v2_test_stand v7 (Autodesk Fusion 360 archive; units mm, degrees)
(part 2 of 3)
sketch "Sketch15" plane through (0, 327.4208, 0) normal (0, 1, 0) x axis (-1, 0, 0)
  line L1 (8.9053, 183.5) -> (8.9053, 201.5)
  line L2 (1.5053, 182.2) -> (7.6053, 182.2)
  line L3 (1.5053, 184.6) -> (1.5053, 182.2)
  line L4 (2.6553, 184.6) -> (1.5053, 184.6)
  line L5 (2.6553, 187.0757) -> (2.6553, 184.6)
  line L6 (1.4897, 188.2414) -> (2.6553, 187.0757)
  line L7 (-4.1375, 188.3) -> (1.3482, 188.3)
  line L8 (-5.4447, 187.0757) -> (-4.279, 188.2414)
  line L9 (-5.4447, 184.6) -> (-5.4447, 187.0757)
  line L10 (-4.2947, 184.6) -> (-5.4447, 184.6)
  line L11 (-4.2947, 182.2) -> (-4.2947, 184.6)
  line L12 (-10.3947, 182.2) -> (-4.2947, 182.2)
  line L13 (-11.6947, 201.5) -> (-11.6947, 183.5)
  line L14 (-4.2947, 202.8) -> (-10.3947, 202.8)
  line L15 (-4.2947, 200.4) -> (-4.2947, 202.8)
  line L16 (-5.4447, 200.4) -> (-4.2947, 200.4)
  line L17 (-5.4447, 197.9243) -> (-5.4447, 200.4)
  line L18 (-4.279, 196.7586) -> (-5.4447, 197.9243)
  line L19 (1.3482, 196.7) -> (-4.1375, 196.7)
  line L20 (2.6553, 197.9243) -> (1.4897, 196.7586)
  line L21 (2.6553, 200.4) -> (2.6553, 197.9243)
  line L22 (1.5053, 200.4) -> (2.6553, 200.4)
  line L23 (1.5053, 202.8) -> (1.5053, 200.4)
  line L24 (7.6053, 202.8) -> (1.5053, 202.8)
  line L25 (-31.6668, 173.4615) -> (-43.4822, 172.9384)
  line L26 (37.2412, 176.2252) -> (39.6909, 169.5703)
  line L27 (-21.0401, 223.4114) -> (18.2508, 223.4114)
  line L28 (-25.1872, 215.4114) -> (22.6618, 215.4114)
  line L29 (-1.3947, 223.4114) -> (-1.2627, 215.4114)
  line L30 (15.6053, 231.4114) -> (-18.3947, 231.4114)
  line L31 (15.6053, 215.4114) -> (15.6053, 231.4114)
  line L32 (-18.3947, 215.4114) -> (15.6053, 215.4114)
  line L33 (-18.3947, 231.4114) -> (-18.3947, 215.4114)
  line L34 (15.6053, 215.4114) -> (-18.3947, 231.4114)
  line L35 (-18.3947, 215.4114) -> (15.6053, 231.4114)
  line L36 (10.9432, 225.8402) -> (-13.7325, 225.8402)
  line L37 (10.9432, 220.9826) -> (10.9432, 225.8402)
  line L38 (-13.7325, 220.9826) -> (10.9432, 220.9826)
  line L39 (-13.7325, 225.8402) -> (-13.7325, 220.9826)
  line L40 (10.9432, 220.9826) -> (-13.7325, 225.8402)
  line L41 (-13.7325, 220.9826) -> (10.9432, 225.8402)
  line L42 (15.8693, 220.9826) -> (-18.3947, 220.9826)
  line L43 (15.8693, 209.8402) -> (15.8693, 220.9826)
  line L44 (-18.3947, 209.8402) -> (15.8693, 209.8402)
  line L45 (-18.3947, 220.9826) -> (-18.3947, 209.8402)
  line L46 (15.8693, 209.8402) -> (-18.3947, 220.9826)
  line L47 (-18.3947, 209.8402) -> (15.8693, 220.9826)
  arc A1 centre (7.6053, 183.5) radius 1.3 clockwise from (8.9053, 183.5) to (7.6053, 182.2)
  arc A2 centre (1.3482, 188.1) radius 0.2 clockwise from (1.3482, 188.3) to (1.4897, 188.2414)
  arc A3 centre (-4.1375, 188.1) radius 0.2 clockwise from (-4.279, 188.2414) to (-4.1375, 188.3)
  arc A4 centre (-10.3947, 183.5) radius 1.3 clockwise from (-10.3947, 182.2) to (-11.6947, 183.5)
  arc A5 centre (-10.3947, 201.5) radius 1.3 clockwise from (-11.6947, 201.5) to (-10.3947, 202.8)
  arc A6 centre (-4.1375, 196.9) radius 0.2 clockwise from (-4.1375, 196.7) to (-4.279, 196.7586)
  arc A7 centre (1.3482, 196.9) radius 0.2 clockwise from (1.4897, 196.7586) to (1.3482, 196.7)
  arc A8 centre (7.6053, 201.5) radius 1.3 clockwise from (7.6053, 202.8) to (8.9053, 201.5)
  arc A9 centre (0, 97.9412) radius 86.6908 clockwise from (37.2412, 176.2252) to (-43.4822, 172.9384)
  arc A10 centre (0, 97.9412) radius 81.8908 clockwise from (39.6909, 169.5703) to (-31.6668, 173.4615)
  arc A11 centre (0, 97.9412) radius 92.5 clockwise from (56.4687, 171.2046) to (-58.7024, 169.4274)
  arc A12 centre (211.2843, 324.6293) radius 217.961 clockwise from (56.4687, 171.2046) to (18.2508, 223.4114)
  arc A13 centre (-216.5788, 319.7006) radius 217.961 clockwise from (-21.0401, 223.4114) to (-58.7024, 169.4274)
  circle C1 centre (0, 97.9412) radius 74.7
  point P53 (22.6618, 215.4114)
  point P54 (-25.1872, 215.4114)
  point P55 (-1.2627, 215.4114)
  point P56 (-1.3947, 223.4114)
  point P61 (-1.3947, 223.4114)
  point P60 (-18.3947, 215.4114)
  point P66 (-1.3947, 223.4114)
  point P71 (-1.2627, 215.4114)
  point P67 (-18.3947, 220.9826)
  point P57 (-18.3947, 231.4114)
  point P58 (15.6053, 231.4114)
  coincident A12 P53
  coincident A13 P54
  horizontal L28
  midpoint L28 P55
  midpoint L27 P56
  horizontal L30
  perpendicular L30 L31
  parallel L30 L32
  parallel L31 L33
  coincident L34 P61
  coincident L35 P61
  coincident P56 P61
  coincident L28 P60
  horizontal L36
  perpendicular L36 L37
  parallel L36 L38
  parallel L37 L39
  coincident L40 P66
  coincident L41 P66
  coincident P61 P66
  horizontal L42
  perpendicular L42 L43
  parallel L42 L44
  parallel L43 L45
  coincident L46 P71
  coincident L47 P71
  coincident L33 P67
  coincident P55 P71
  dimension "d105" distance P57 P58 = 34
  dimension "d106" distance L27 P60 = 8
extrude "Extrude15" cut sketch "Sketch15" profile of L27 L28 L29 L31 L32 L33 L37 L38 L39 L42 L43 L45 against normal blind 50.007
chamfer "Chamfer6" distance 2
sketch "Sketch16" plane through (0, 277.4138, 0) normal (0, 1, 0) x axis (-1, 0, 0)
  line L1 (15.8693, 217.4114) -> (13.8693, 215.4114)
  line L2 (15.8693, 220.9826) -> (15.8693, 217.4114)
  line L3 (12.9432, 220.9826) -> (15.8693, 220.9826)
  line L4 (10.9432, 222.9826) -> (12.9432, 220.9826)
  line L5 (10.9432, 223.4114) -> (10.9432, 222.9826)
  line L6 (-13.7325, 223.4114) -> (10.9432, 223.4114)
  line L7 (-13.7325, 222.9826) -> (-13.7325, 223.4114)
  line L8 (-15.7325, 220.9826) -> (-13.7325, 222.9826)
  line L9 (-18.3947, 220.9826) -> (-15.7325, 220.9826)
  line L10 (-18.3947, 217.4114) -> (-18.3947, 220.9826)
  line L11 (-16.3947, 215.4114) -> (-18.3947, 217.4114)
  line L12 (13.8693, 215.4114) -> (-16.3947, 215.4114)
  line L13 (-1.2627, 215.4114) -> (-1.3947, 223.4114)
  line L14 (9.9529, 231.4114) -> (-12.7422, 231.4114)
  line L15 (9.9529, 215.4114) -> (9.9529, 231.4114)
  line L16 (-12.7422, 215.4114) -> (9.9529, 215.4114)
  line L17 (-12.7422, 231.4114) -> (-12.7422, 215.4114)
  line L18 (9.9529, 215.4114) -> (-12.7422, 231.4114)
  line L19 (-12.7422, 215.4114) -> (9.9529, 231.4114)
  line L20 (-16.3947, 215.4114) -> (13.8693, 215.4114)
  point P14 (-1.3947, 223.4114)
  point P15 (-1.2627, 215.4114)
  point P20 (-1.3947, 223.4114)
  point P19 (-12.7422, 215.4114)
  coincident L6 P14
  midpoint L12 P15
  midpoint L6 P14
  horizontal L14
  perpendicular L14 L15
  parallel L14 L16
  parallel L15 L17
  coincident L18 P20
  coincident L19 P20
  coincident P14 P20
  coincident P19 L20
extrude "Extrude16" cut sketch "Sketch16" profile of L6 L12 L13 L15 L16 L17 L20 against normal blind 13.004
fillet "Fillet11" radius 1
component_insert "Component Insert1"
sketch "Sketch1" plane through (0, 277.4138, 0) normal (0, 1, 0) x axis (-1, 0, 0)
  line L1 (-21.3476, 215.4114) -> (-24.5858, 215.4114)
  line L2 (-21.3476, 223.4114) -> (-21.3476, 215.4114)
  line L3 (-23.1586, 223.4114) -> (-21.3476, 223.4114)
  line L4 (-24.0449, 221.2755) -> (-22.3378, 222.9826)
  line L5 (-27, 220.9826) -> (-24.752, 220.9826)
  line L6 (-27, 217.8256) -> (-27, 220.9826)
  line L7 (-25.2929, 215.7043) -> (-26.7071, 217.1185)
  line L8 (7.2639, 220.9826) -> (7.2639, 217.8256)
  line L9 (4.3378, 220.9826) -> (7.2639, 220.9826)
  line L10 (2.3378, 222.9826) -> (4.3378, 220.9826)
  line L11 (1.3476, 223.4114) -> (3.1586, 223.4114)
  line L12 (1.3476, 215.4114) -> (1.3476, 223.4114)
  line L13 (4.8497, 215.4114) -> (1.3476, 215.4114)
  line L14 (6.971, 217.1185) -> (5.5568, 215.7043)
  line L15 (-21.3476, 223.4114) -> (1.3476, 223.4114)
  line L16 (-21.3476, 215.4114) -> (1.3476, 215.4114)
  line L17 (6.865, 217.2246) -> (5.4508, 215.8104)
  line L18 (7.1139, 220.8326) -> (7.1139, 217.8256)
  line L19 (4.2757, 220.8326) -> (7.1139, 220.8326)
  line L20 (2.148, 222.9602) -> (4.2757, 220.8326)
  line L21 (1.4976, 223.2614) -> (2.384, 223.2614)
  line L22 (1.4976, 215.5614) -> (1.4976, 223.2614)
  line L23 (4.8497, 215.5614) -> (1.4976, 215.5614)
  line L24 (-21.3476, 215.5614) -> (1.3476, 215.5614)
  line L25 (-21.3476, 215.5614) -> (-24.5858, 215.5614)
  line L26 (-25.1868, 215.8104) -> (-26.601, 217.2246)
  line L27 (-26.85, 217.8256) -> (-26.85, 220.8326)
  line L28 (-26.85, 220.8326) -> (-24.752, 220.8326)
  line L29 (-23.9389, 221.1694) -> (-22.148, 222.9602)
  line L30 (-22.384, 223.2614) -> (-21.3476, 223.2614)
  line L31 (-21.3476, 223.2614) -> (1.3476, 223.2614)
  line L32 (1.4976, 215.5614) -> (1.3476, 215.5614)
  line L33 (1.4976, 223.2614) -> (1.3476, 223.2614)
  arc A1 centre (-24.5858, 216.4114) radius 1 clockwise from (-24.5858, 215.4114) to (-25.2929, 215.7043)
  arc A2 centre (-23.1586, 222.4114) radius 1 clockwise from (-23.1586, 223.4114) to (-22.3378, 222.9826)
  arc A3 centre (-24.752, 221.9826) radius 1 clockwise from (-24.0449, 221.2755) to (-24.752, 220.9826)
  arc A4 centre (-26, 217.8256) radius 1 clockwise from (-26.7071, 217.1185) to (-27, 217.8256)
  arc A5 centre (6.2639, 217.8256) radius 1 clockwise from (7.2639, 217.8256) to (6.971, 217.1185)
  arc A6 centre (3.1586, 222.4114) radius 1 clockwise from (2.3378, 222.9826) to (3.1586, 223.4114)
  arc A7 centre (4.8497, 216.4114) radius 1 clockwise from (5.5568, 215.7043) to (4.8497, 215.4114)
  arc A8 centre (6.2639, 217.8256) radius 0.85 clockwise from (7.1139, 217.8256) to (6.865, 217.2246)
  arc A9 centre (3.1586, 222.4114) radius 1.15 clockwise from (2.148, 222.9602) to (2.384, 223.2614)
  arc A10 centre (4.8497, 216.4114) radius 0.85 clockwise from (5.4508, 215.8104) to (4.8497, 215.5614)
  arc A11 centre (-24.5858, 216.4114) radius 0.85 clockwise from (-24.5858, 215.5614) to (-25.1868, 215.8104)
  arc A12 centre (-26, 217.8256) radius 0.85 clockwise from (-26.601, 217.2246) to (-26.85, 217.8256)
  arc A13 centre (-24.752, 221.9826) radius 1.15 clockwise from (-23.9389, 221.1694) to (-24.752, 220.8326)
  arc A14 centre (-23.1586, 222.4114) radius 1.15 clockwise from (-22.384, 223.2614) to (-22.148, 222.9602)
  point P25 (1.3476, 223.4114)
  point P30 (1.3476, 223.4114)
  point P6 (-21.3476, 223.4114)
  point P31 (-21.3476, 223.4114)
  point P26 (1.3476, 215.4114)
  point P32 (1.3476, 215.4114)
  point P5 (-21.3476, 215.4114)
  point P33 (-21.3476, 215.4114)
  coincident P25 P30
  coincident P6 P31
  coincident P26 P32
  coincident P5 P33
  perpendicular L22 L33
  dimension "d114" = -0.15
  dimension "d115" = -0.15
extrude "Extrude1" new body sketch "Sketch1" profile of L2 L12 A10 L19 L18 A9 L20 L23 L21 A8 L22 L17 L31 L30 L28 L29 A13 L24 A12 L26 A11 L27 L25 A14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 along normal blind 50.007
work_plane "WorkPlane1" AlongDistance 0
sketch "Sketch2" plane through (0, 320.143, 235.208) normal (0, -0.8059, -0.5921) x axis (-1, 0, 0)
  line L1 (-13.0817, -59.9833) -> (-18.9746, -59.9833)
  line L2 (-12.5817, -57.9833) -> (-12.5817, -59.4833)
  line L3 (-9.0817, -57.4833) -> (-12.0817, -57.4833)
  line L4 (-8.5817, -59.4833) -> (-8.5817, -57.9833)
  line L5 (-2.1888, -59.9833) -> (-8.0817, -59.9833)
  line L6 (16.5218, -41.4797) -> (-1.8353, -59.8369)
  line L7 (16.6683, -38.5404) -> (16.6683, -41.1262)
  line L8 (-1.9817, -19.6833) -> (16.5218, -38.1869)
  line L9 (-8.5817, -19.6833) -> (-1.9817, -19.6833)
  line L10 (-8.5817, -23.1833) -> (-8.5817, -19.6833)
  line L11 (-12.5817, -23.1833) -> (-8.5817, -23.1833)
  line L12 (-12.5817, -19.6833) -> (-12.5817, -23.1833)
  line L13 (-19.1817, -19.6833) -> (-12.5817, -19.6833)
  line L14 (-37.6853, -38.1869) -> (-19.1817, -19.6833)
  line L15 (-37.8317, -41.1262) -> (-37.8317, -38.5404)
  line L16 (-19.3282, -59.8369) -> (-37.6853, -41.4797)
  line L17 (21.0013, -38.5404) -> (21.0013, -41.1262)
  line L18 (-0.1869, -15.3502) -> (19.5858, -35.1229)
  line L19 (-8.2487, -15.3502) -> (-0.1869, -15.3502)
  line L20 (-12.9148, -15.3502) -> (-8.2487, -15.3502)
  line L21 (-20.9765, -15.3502) -> (-12.9148, -15.3502)
  line L22 (-40.7492, -35.1229) -> (-20.9765, -15.3502)
  line L23 (-42.1648, -41.1262) -> (-42.1648, -38.5404)
  line L24 (-22.3921, -62.9008) -> (-40.7492, -44.5437)
  line L25 (-13.0817, -64.3164) -> (-18.9746, -64.3164)
  line L26 (-2.1888, -64.3164) -> (-8.0817, -64.3164)
  line L27 (19.5858, -44.5437) -> (1.2287, -62.9008)
  line L28 (16.8683, -38.5404) -> (16.8683, -41.1262)
  line L29 (-1.8989, -19.4833) -> (16.6632, -38.0454)
  line L30 (-8.7817, -19.4833) -> (-1.8989, -19.4833)
  line L31 (-8.7817, -22.9833) -> (-8.7817, -19.4833)
  line L32 (-12.3817, -22.9833) -> (-8.7817, -22.9833)
  line L33 (-12.3817, -19.4833) -> (-12.3817, -22.9833)
  line L34 (-19.2646, -19.4833) -> (-12.3817, -19.4833)
  line L35 (-37.8267, -38.0454) -> (-19.2646, -19.4833)
  line L36 (-38.0317, -41.1262) -> (-38.0317, -38.5404)
  line L37 (-19.4696, -59.9783) -> (-37.8267, -41.6212)
  line L38 (-13.0817, -60.1833) -> (-18.9746, -60.1833)
  line L39 (-12.3817, -57.9833) -> (-12.3817, -59.4833)
  line L40 (-9.0817, -57.6833) -> (-12.0817, -57.6833)
  line L41 (-8.7817, -59.4833) -> (-8.7817, -57.9833)
  line L42 (-2.1888, -60.1833) -> (-8.0817, -60.1833)
  line L43 (16.6632, -41.6212) -> (-1.6939, -59.9783)
  arc A1 centre (-10.5817, -39.8333) radius 14.5 clockwise from (-23.9958, -34.3276) to (-24.0005, -45.3276)
  arc A2 centre (-13.0817, -59.4833) radius 0.5 clockwise from (-12.5817, -59.4833) to (-13.0817, -59.9833)
  arc A3 centre (-12.0817, -57.9833) radius 0.5 clockwise from (-12.5817, -57.9833) to (-12.0817, -57.4833)
  arc A4 centre (-9.0817, -57.9833) radius 0.5 clockwise from (-9.0817, -57.4833) to (-8.5817, -57.9833)
  arc A5 centre (-8.0817, -59.4833) radius 0.5 clockwise from (-8.0817, -59.9833) to (-8.5817, -59.4833)
  arc A6 centre (-2.1888, -59.4833) radius 0.5 clockwise from (-1.8353, -59.8369) to (-2.1888, -59.9833)
  arc A7 centre (16.1683, -41.1262) radius 0.5 clockwise from (16.6683, -41.1262) to (16.5218, -41.4797)
  arc A8 centre (16.1683, -38.5404) radius 0.5 clockwise from (16.5218, -38.1869) to (16.6683, -38.5404)
  arc A9 centre (-37.3317, -38.5404) radius 0.5 clockwise from (-37.8317, -38.5404) to (-37.6853, -38.1869)
  arc A10 centre (-37.3317, -41.1262) radius 0.5 clockwise from (-37.6853, -41.4797) to (-37.8317, -41.1262)
  arc A11 centre (-18.9746, -59.4833) radius 0.5 clockwise from (-18.9746, -59.9833) to (-19.3282, -59.8369)
  circle C1 centre (-34.8317, -39.8333) radius 1.6
  circle C2 centre (13.6683, -39.8333) radius 1.6
  circle C3 centre (-10.5817, -39.8333) radius 14.5
  arc A12 centre (16.1683, -38.5404) radius 4.8331 clockwise from (19.5858, -35.1229) to (21.0013, -38.5404)
  arc A13 centre (-37.3317, -38.5404) radius 4.8331 clockwise from (-42.1648, -38.5404) to (-40.7492, -35.1229)
  arc A14 centre (-37.3317, -41.1262) radius 4.8331 clockwise from (-40.7492, -44.5437) to (-42.1648, -41.1262)
  arc A15 centre (-18.9746, -59.4833) radius 4.8331 clockwise from (-18.9746, -64.3164) to (-22.3921, -62.9008)
  arc A16 centre (-13.0817, -59.4833) radius 4.8331 clockwise from (-10.5817, -63.6195) to (-13.0817, -64.3164)
  arc A17 centre (-8.0817, -59.4833) radius 4.8331 clockwise from (-8.0817, -64.3164) to (-10.5817, -63.6195)
  arc A18 centre (-2.1888, -59.4833) radius 4.8331 clockwise from (1.2287, -62.9008) to (-2.1888, -64.3164)
  arc A19 centre (16.1683, -41.1262) radius 4.8331 clockwise from (21.0013, -41.1262) to (19.5858, -44.5437)
  arc A20 centre (16.1683, -38.5404) radius 0.7 clockwise from (16.6632, -38.0454) to (16.8683, -38.5404)
  arc A21 centre (-37.3317, -38.5404) radius 0.7 clockwise from (-38.0317, -38.5404) to (-37.8267, -38.0454)
  arc A22 centre (-37.3317, -41.1262) radius 0.7 clockwise from (-37.8267, -41.6212) to (-38.0317, -41.1262)
  arc A23 centre (-18.9746, -59.4833) radius 0.7 clockwise from (-18.9746, -60.1833) to (-19.4696, -59.9783)
  arc A24 centre (-13.0817, -59.4833) radius 0.7 clockwise from (-12.3817, -59.4833) to (-13.0817, -60.1833)
  arc A25 centre (-12.0817, -57.9833) radius 0.3 clockwise from (-12.3817, -57.9833) to (-12.0817, -57.6833)
  arc A26 centre (-9.0817, -57.9833) radius 0.3 clockwise from (-9.0817, -57.6833) to (-8.7817, -57.9833)
  arc A27 centre (-8.0817, -59.4833) radius 0.7 clockwise from (-8.0817, -60.1833) to (-8.7817, -59.4833)
  arc A28 centre (-2.1888, -59.4833) radius 0.7 clockwise from (-1.6939, -59.9783) to (-2.1888, -60.1833)
  arc A29 centre (16.1683, -41.1262) radius 0.7 clockwise from (16.8683, -41.1262) to (16.6632, -41.6212)
  circle C4 centre (-10.5817, -39.8333) radius 17.1851
  dimension "d119" = 0.2
  dimension "d120" = 4.3331
  dimension "d121" = 2.6851
extrude "Extrude2" new body sketch "Sketch2" profile of L1 A2 L2 A3 L3 A4 L4 A5 L5 A6 L6 A7 L7 A8 L8 L9 L10 L12 L13 L14 A9 L15 A10 L16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 along normal blind 36.088
extrude "Extrude3" add sketch "Sketch2" profile of A29 L39 L35 A24 L40 A20 A27 L43 A22 L41 L38 A23 L30 L37 L36 L34 A28 L33 L31 L42 A21 L29 L28 A19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 against normal blind 2.6453
loft "Loft1"
fillet "Fillet1" radius 20
position "Position4"
position "Position5"
position "Position6"
position "Position7"
sketch "Sketch4" plane through (0, 24.3589, 0) normal (0, -1, 0) x axis (1, 0, 0)
  line L1 (20, 201.5) -> (20, 195.7)
  line L2 (13.2, 202.5) -> (19, 202.5)
  line L3 (13.2, 200.7) -> (13.2, 202.5)
  line L4 (14.95, 200.7) -> (13.2, 200.7)
  line L5 (15.45, 199.1071) -> (15.45, 200.2)
  line L6 (13.0964, 196.5464) -> (15.3036, 198.7536)
  line L7 (7.2571, 196.4) -> (12.7429, 196.4)
  line L8 (4.6964, 198.7536) -> (6.9036, 196.5464)
  line L9 (4.55, 200.2) -> (4.55, 199.1071)
  line L10 (6.8, 200.7) -> (5.05, 200.7)
  line L11 (6.8, 202.5) -> (6.8, 200.7)
  line L12 (1, 202.5) -> (6.8, 202.5)
  line L13 (0, 195.7) -> (0, 201.5)
  line L14 (1.8, 195.7) -> (0, 195.7)
  line L15 (1.8, 197.45) -> (1.8, 195.7)
  line L16 (3.3929, 197.95) -> (2.3, 197.95)
  line L17 (5.9536, 195.5964) -> (3.7464, 197.8036)
  line L18 (6.1, 189.7571) -> (6.1, 195.2429)
  line L19 (3.7464, 187.1964) -> (5.9536, 189.4036)
  line L20 (2.3, 187.05) -> (3.3929, 187.05)
  line L21 (1.8, 189.3) -> (1.8, 187.55)
  line L22 (0, 189.3) -> (1.8, 189.3)
  line L23 (0, 183.5) -> (0, 189.3)
  line L24 (6.8, 182.5) -> (1, 182.5)
  line L25 (6.8, 184.3) -> (6.8, 182.5)
  line L26 (5.05, 184.3) -> (6.8, 184.3)
  line L27 (4.55, 185.8929) -> (4.55, 184.8)
  line L28 (6.9036, 188.4536) -> (4.6964, 186.2464)
  line L29 (12.7429, 188.6) -> (7.2571, 188.6)
  line L30 (15.3036, 186.2464) -> (13.0964, 188.4536)
  line L31 (15.45, 184.8) -> (15.45, 185.8929)
  line L32 (13.2, 184.3) -> (14.95, 184.3)
  line L33 (13.2, 182.5) -> (13.2, 184.3)
  line L34 (19, 182.5) -> (13.2, 182.5)
  line L35 (20, 189.3) -> (20, 183.5)
  line L36 (18.2, 189.3) -> (20, 189.3)
  line L37 (18.2, 187.55) -> (18.2, 189.3)
  line L38 (16.6071, 187.05) -> (17.7, 187.05)
  line L39 (14.0464, 189.4036) -> (16.2536, 187.1964)
  line L40 (13.9, 195.2429) -> (13.9, 189.7571)
  line L41 (16.2536, 197.8036) -> (14.0464, 195.5964)
  line L42 (17.7, 197.95) -> (16.6071, 197.95)
  line L43 (18.2, 195.7) -> (18.2, 197.45)
  line L44 (20, 195.7) -> (18.2, 195.7)
  arc A1 centre (19, 201.5) radius 1 clockwise from (19, 202.5) to (20, 201.5)
  arc A2 centre (14.95, 200.2) radius 0.5 clockwise from (14.95, 200.7) to (15.45, 200.2)
  arc A3 centre (14.95, 199.1071) radius 0.5 clockwise from (15.45, 199.1071) to (15.3036, 198.7536)
  arc A4 centre (12.7429, 196.9) radius 0.5 clockwise from (13.0964, 196.5464) to (12.7429, 196.4)
  arc A5 centre (7.2571, 196.9) radius 0.5 clockwise from (7.2571, 196.4) to (6.9036, 196.5464)
  arc A6 centre (5.05, 199.1071) radius 0.5 clockwise from (4.6964, 198.7536) to (4.55, 199.1071)
  arc A7 centre (5.05, 200.2) radius 0.5 clockwise from (4.55, 200.2) to (5.05, 200.7)
  arc A8 centre (1, 201.5) radius 1 clockwise from (0, 201.5) to (1, 202.5)
  arc A9 centre (2.3, 197.45) radius 0.5 clockwise from (1.8, 197.45) to (2.3, 197.95)
  arc A10 centre (3.3929, 197.45) radius 0.5 clockwise from (3.3929, 197.95) to (3.7464, 197.8036)
  arc A11 centre (5.6, 195.2429) radius 0.5 clockwise from (5.9536, 195.5964) to (6.1, 195.2429)
  arc A12 centre (5.6, 189.7571) radius 0.5 clockwise from (6.1, 189.7571) to (5.9536, 189.4036)
  arc A13 centre (3.3929, 187.55) radius 0.5 clockwise from (3.7464, 187.1964) to (3.3929, 187.05)
  arc A14 centre (2.3, 187.55) radius 0.5 clockwise from (2.3, 187.05) to (1.8, 187.55)
  arc A15 centre (1, 183.5) radius 1 clockwise from (1, 182.5) to (0, 183.5)
  arc A16 centre (5.05, 184.8) radius 0.5 clockwise from (5.05, 184.3) to (4.55, 184.8)
  arc A17 centre (5.05, 185.8929) radius 0.5 clockwise from (4.55, 185.8929) to (4.6964, 186.2464)
  arc A18 centre (7.2571, 188.1) radius 0.5 clockwise from (6.9036, 188.4536) to (7.2571, 188.6)
  arc A19 centre (12.7429, 188.1) radius 0.5 clockwise from (12.7429, 188.6) to (13.0964, 188.4536)
  arc A20 centre (14.95, 185.8929) radius 0.5 clockwise from (15.3036, 186.2464) to (15.45, 185.8929)
  arc A21 centre (14.95, 184.8) radius 0.5 clockwise from (15.45, 184.8) to (14.95, 184.3)
  arc A22 centre (19, 183.5) radius 1 clockwise from (20, 183.5) to (19, 182.5)
  arc A23 centre (17.7, 187.55) radius 0.5 clockwise from (18.2, 187.55) to (17.7, 187.05)
  arc A24 centre (16.6071, 187.55) radius 0.5 clockwise from (16.6071, 187.05) to (16.2536, 187.1964)
  arc A25 centre (14.4, 189.7571) radius 0.5 clockwise from (14.0464, 189.4036) to (13.9, 189.7571)
  arc A26 centre (14.4, 195.2429) radius 0.5 clockwise from (13.9, 195.2429) to (14.0464, 195.5964)
  arc A27 centre (16.6071, 197.45) radius 0.5 clockwise from (16.2536, 197.8036) to (16.6071, 197.95)
  arc A28 centre (17.7, 197.45) radius 0.5 clockwise from (17.7, 197.95) to (18.2, 197.45)
  circle C1 centre (10, 192.5) radius 2.5
  circle C2 centre (9.0158, 20.6671) radius 78.5
  circle C3 centre (9.0158, 20.6671) radius 68.5
  circle C4 centre (9.0158, 20.6671) radius 82.5
  dimension "d136" = -10
  dimension "d137" = 4
extrude "Extrude4" new body sketch "Sketch4" profile of C2 C3 C4 along normal blind 26.1
sketch "Sketch5" plane through (0, 24.3589, 0) normal (0, 1, 0) x axis (-1, 0, 0)
  circle C1 centre (-9.0158, 20.6671) radius 78.5
  circle C2 centre (-9.0158, 20.6671) radius 78.8
  circle C3 centre (-9.0158, 20.6671) radius 82.5
  dimension "d140" = 0.3
extrude "Extrude5" add sketch "Sketch5" profile of C2 C3 along normal blind 8.212
sketch "Sketch6" plane through (0, -1.7411, 0) normal (0, -1, 0) x axis (1, 0, 0)
  line L1 (48.5935, -51.7197) -> (9.0158, 20.6671)
  line L2 (91.5158, 20.6671) -> (-73.4842, 20.6671)
  line L3 (48.5935, 93.054) -> (9.0158, 20.6671)
  line L4 (9.0158, -47.8329) -> (9.0158, 89.1671)
  line L5 (-30.5619, -51.7197) -> (9.0158, 20.6671)
  line L6 (-30.5619, 93.054) -> (9.0158, 20.6671)
  circle C1 centre (9.0158, 20.6671) radius 68.5
  circle C2 centre (9.0158, 20.6671) radius 82.5
  point P2 (9.0158, 20.6671)
  point P3 (9.0158, 20.6671)
  point P4 (48.5935, -51.7197)
  point P5 (-73.4842, 20.6671)
  point P6 (91.5158, 20.6671)
  point P7 (9.0158, 20.6671)
  point P8 (48.5935, 93.054)
  point P9 (9.0158, 89.1671)
  point P10 (9.0158, -47.8329)
  point P11 (9.0158, 20.6671)
  point P12 (-30.5619, -51.7197)
  point P13 (9.0158, 20.6671)
  point P14 (-30.5619, 93.054)
  coincident P2 P3
  coincident C2 P4
  coincident C2 P5
  coincident C2 P6
  horizontal L2
  midpoint P2 L2
  symmetric P3 L2 P7
  symmetric P4 L2 P8
  coincident C1 P9
  coincident C1 P10
  midpoint P7 L4
  vertical L4
  symmetric P3 L4 P11
  symmetric P4 L4 P12
  symmetric P7 L4 P13
  symmetric P8 L4 P14
extrude "Extrude6" cut sketch "Sketch6" profile of C1 C2 L1 L3 L5 L6 against normal blind 19.287
fillet "Fillet1" radius 54.648
sketch "Sketch7" plane through (0, -1.7411, 0) normal (0, -1, 0) x axis (1, 0, 0)
  line L1 (20, 201.5) -> (20, 195.7)
  line L2 (13.2, 202.5) -> (19, 202.5)
  line L3 (13.2, 200.7) -> (13.2, 202.5)
  line L4 (14.95, 200.7) -> (13.2, 200.7)
  line L5 (15.45, 199.1071) -> (15.45, 200.2)
  line L6 (13.0964, 196.5464) -> (15.3036, 198.7536)
  line L7 (7.2571, 196.4) -> (12.7429, 196.4)
  line L8 (4.6964, 198.7536) -> (6.9036, 196.5464)
  line L9 (4.55, 200.2) -> (4.55, 199.1071)
  line L10 (6.8, 200.7) -> (5.05, 200.7)
  line L11 (6.8, 202.5) -> (6.8, 200.7)
  line L12 (1, 202.5) -> (6.8, 202.5)
  line L13 (0, 195.7) -> (0, 201.5)
  line L14 (1.8, 195.7) -> (0, 195.7)
  line L15 (1.8, 197.45) -> (1.8, 195.7)
  line L16 (3.3929, 197.95) -> (2.3, 197.95)
  line L17 (5.9536, 195.5964) -> (3.7464, 197.8036)
  line L18 (6.1, 189.7571) -> (6.1, 195.2429)
  line L19 (3.7464, 187.1964) -> (5.9536, 189.4036)
  line L20 (2.3, 187.05) -> (3.3929, 187.05)
  line L21 (1.8, 189.3) -> (1.8, 187.55)
  line L22 (0, 189.3) -> (1.8, 189.3)
  line L23 (0, 183.5) -> (0, 189.3)
  line L24 (6.8, 182.5) -> (1, 182.5)
  line L25 (6.8, 184.3) -> (6.8, 182.5)
  line L26 (5.05, 184.3) -> (6.8, 184.3)
  line L27 (4.55, 185.8929) -> (4.55, 184.8)
  line L28 (6.9036, 188.4536) -> (4.6964, 186.2464)
  line L29 (12.7429, 188.6) -> (7.2571, 188.6)
  line L30 (15.3036, 186.2464) -> (13.0964, 188.4536)
  line L31 (15.45, 184.8) -> (15.45, 185.8929)
  line L32 (13.2, 184.3) -> (14.95, 184.3)
  line L33 (13.2, 182.5) -> (13.2, 184.3)
  line L34 (19, 182.5) -> (13.2, 182.5)
  line L35 (20, 189.3) -> (20, 183.5)
  line L36 (18.2, 189.3) -> (20, 189.3)
  line L37 (18.2, 187.55) -> (18.2, 189.3)
  line L38 (16.6071, 187.05) -> (17.7, 187.05)
  line L39 (14.0464, 189.4036) -> (16.2536, 187.1964)
  line L40 (13.9, 195.2429) -> (13.9, 189.7571)
  line L41 (16.2536, 197.8036) -> (14.0464, 195.5964)
  line L42 (17.7, 197.95) -> (16.6071, 197.95)
  line L43 (18.2, 195.7) -> (18.2, 197.45)
  line L44 (20, 195.7) -> (18.2, 195.7)
  line L45 (-23.8456, 80.7701) -> (-30.5619, 93.054)
  line L46 (48.5935, 93.054) -> (41.8773, 80.7701)
  line L47 (48.5935, 224.2124) -> (48.5935, 93.054)
  line L48 (-1.3476, 223.4114) -> (-9.6455, 223.4114)
  line L49 (-30.5619, 224.2124) -> (48.5935, 224.2124)
  line L50 (-30.5619, 93.054) -> (-30.5619, 224.2124)
  arc A1 centre (19, 201.5) radius 1 clockwise from (19, 202.5) to (20, 201.5)
  arc A2 centre (14.95, 200.2) radius 0.5 clockwise from (14.95, 200.7) to (15.45, 200.2)
  arc A3 centre (14.95, 199.1071) radius 0.5 clockwise from (15.45, 199.1071) to (15.3036, 198.7536)
  arc A4 centre (12.7429, 196.9) radius 0.5 clockwise from (13.0964, 196.5464) to (12.7429, 196.4)
  arc A5 centre (7.2571, 196.9) radius 0.5 clockwise from (7.2571, 196.4) to (6.9036, 196.5464)
  arc A6 centre (5.05, 199.1071) radius 0.5 clockwise from (4.6964, 198.7536) to (4.55, 199.1071)
  arc A7 centre (5.05, 200.2) radius 0.5 clockwise from (4.55, 200.2) to (5.05, 200.7)
  arc A8 centre (1, 201.5) radius 1 clockwise from (0, 201.5) to (1, 202.5)
  arc A9 centre (2.3, 197.45) radius 0.5 clockwise from (1.8, 197.45) to (2.3, 197.95)
  arc A10 centre (3.3929, 197.45) radius 0.5 clockwise from (3.3929, 197.95) to (3.7464, 197.8036)
  arc A11 centre (5.6, 195.2429) radius 0.5 clockwise from (5.9536, 195.5964) to (6.1, 195.2429)
  arc A12 centre (5.6, 189.7571) radius 0.5 clockwise from (6.1, 189.7571) to (5.9536, 189.4036)
  arc A13 centre (3.3929, 187.55) radius 0.5 clockwise from (3.7464, 187.1964) to (3.3929, 187.05)
  arc A14 centre (2.3, 187.55) radius 0.5 clockwise from (2.3, 187.05) to (1.8, 187.55)
  arc A15 centre (1, 183.5) radius 1 clockwise from (1, 182.5) to (0, 183.5)
  arc A16 centre (5.05, 184.8) radius 0.5 clockwise from (5.05, 184.3) to (4.55, 184.8)
  arc A17 centre (5.05, 185.8929) radius 0.5 clockwise from (4.55, 185.8929) to (4.6964, 186.2464)
  arc A18 centre (7.2571, 188.1) radius 0.5 clockwise from (6.9036, 188.4536) to (7.2571, 188.6)
  arc A19 centre (12.7429, 188.1) radius 0.5 clockwise from (12.7429, 188.6) to (13.0964, 188.4536)
  arc A20 centre (14.95, 185.8929) radius 0.5 clockwise from (15.3036, 186.2464) to (15.45, 185.8929)
  arc A21 centre (14.95, 184.8) radius 0.5 clockwise from (15.45, 184.8) to (14.95, 184.3)
  arc A22 centre (19, 183.5) radius 1 clockwise from (20, 183.5) to (19, 182.5)
  arc A23 centre (17.7, 187.55) radius 0.5 clockwise from (18.2, 187.55) to (17.7, 187.05)
  arc A24 centre (16.6071, 187.55) radius 0.5 clockwise from (16.6071, 187.05) to (16.2536, 187.1964)
  arc A25 centre (14.4, 189.7571) radius 0.5 clockwise from (14.0464, 189.4036) to (13.9, 189.7571)
  arc A26 centre (14.4, 195.2429) radius 0.5 clockwise from (13.9, 195.2429) to (14.0464, 195.5964)
  arc A27 centre (16.6071, 197.45) radius 0.5 clockwise from (16.2536, 197.8036) to (16.6071, 197.95)
  arc A28 centre (17.7, 197.45) radius 0.5 clockwise from (17.7, 197.95) to (18.2, 197.45)
  circle C1 centre (10, 192.5) radius 2.5
  arc A29 centre (9.0158, 20.6671) radius 68.5 clockwise from (-23.8456, 80.7701) to (41.8773, 80.7701)
  arc A30 centre (9.0158, 20.6671) radius 82.5 clockwise from (-30.5619, 93.054) to (48.5935, 93.054)
  point P107 (48.5935, 93.054)
  point P108 (48.5935, 93.054)
  point P103 (-30.5619, 93.054)
  point P113 (-30.5619, 93.054)
  coincident P107 P108
  parallel L48 L49
  coincident P103 P113
  vertical L50
  vertical L47
extrude "Extrude7" add sketch "Sketch7" profile of L1 A1 L2 L3 L4 A2 L5 A3 L6 A4 L7 A5 L8 A6 L9 A7 L10 L11 L12 A8 L13 L14 L15 A9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 against normal blind 34.312
fillet "Fillet3" radius 15
work_plane "WorkPlane1" AlongDistance -116.2199
sketch "Sketch8" plane through (0, 32.5709, 0) normal (0, 1, 0) x axis (-1, 0, 0)
  line L1 (-48.5935, 93.054) -> (-48.5935, 209.2124)
  line L2 (30.5619, 209.2124) -> (30.5619, 93.054)
  line L3 (-33.5935, 224.2124) -> (15.5619, 224.2124)
  line L4 (-18.2, 195.7) -> (-18.2, 197.45)
  line L5 (-20, 195.7) -> (-18.2, 195.7)
  line L6 (-20, 201.5) -> (-20, 195.7)
  line L7 (-13.2, 202.5) -> (-19, 202.5)
  line L8 (-13.2, 200.7) -> (-13.2, 202.5)
  line L9 (-14.95, 200.7) -> (-13.2, 200.7)
  line L10 (-15.45, 199.1071) -> (-15.45, 200.2)
  line L11 (-13.0964, 196.5464) -> (-15.3036, 198.7536)
  line L12 (-7.2571, 196.4) -> (-12.7429, 196.4)
  line L13 (-4.6964, 198.7536) -> (-6.9036, 196.5464)
  line L14 (-4.55, 200.2) -> (-4.55, 199.1071)
  line L15 (-6.8, 200.7) -> (-5.05, 200.7)
  line L16 (-6.8, 202.5) -> (-6.8, 200.7)
  line L17 (-1, 202.5) -> (-6.8, 202.5)
  line L18 (0, 195.7) -> (0, 201.5)
  line L19 (-1.8, 195.7) -> (0, 195.7)
  line L20 (-1.8, 197.45) -> (-1.8, 195.7)
  line L21 (-3.3929, 197.95) -> (-2.3, 197.95)
  line L22 (-5.9536, 195.5964) -> (-3.7464, 197.8036)
  line L23 (-6.1, 189.7571) -> (-6.1, 195.2429)
  line L24 (-3.7464, 187.1964) -> (-5.9536, 189.4036)
  line L25 (-2.3, 187.05) -> (-3.3929, 187.05)
  line L26 (-1.8, 189.3) -> (-1.8, 187.55)
  line L27 (0, 189.3) -> (-1.8, 189.3)
  line L28 (0, 183.5) -> (0, 189.3)
  line L29 (-6.8, 182.5) -> (-1, 182.5)
  line L30 (-6.8, 184.3) -> (-6.8, 182.5)
  line L31 (-5.05, 184.3) -> (-6.8, 184.3)
  line L32 (-4.55, 185.8929) -> (-4.55, 184.8)
  line L33 (-6.9036, 188.4536) -> (-4.6964, 186.2464)
  line L34 (-12.7429, 188.6) -> (-7.2571, 188.6)
  line L35 (-15.3036, 186.2464) -> (-13.0964, 188.4536)
  line L36 (-15.45, 184.8) -> (-15.45, 185.8929)
  line L37 (-13.2, 184.3) -> (-14.95, 184.3)
  line L38 (-13.2, 182.5) -> (-13.2, 184.3)
  line L39 (-19, 182.5) -> (-13.2, 182.5)
  line L40 (-20, 189.3) -> (-20, 183.5)
  line L41 (-18.2, 189.3) -> (-20, 189.3)
  line L42 (-18.2, 187.55) -> (-18.2, 189.3)
  line L43 (-16.6071, 187.05) -> (-17.7, 187.05)
  line L44 (-14.0464, 189.4036) -> (-16.2536, 187.1964)
  line L45 (-13.9, 195.2429) -> (-13.9, 189.7571)
  line L46 (-16.2536, 197.8036) -> (-14.0464, 195.5964)
  line L47 (-17.7, 197.95) -> (-16.6071, 197.95)
  line L48 (-48.5935, 135.0766) -> (30.5619, 135.0766)
  arc A1 centre (-33.5935, 209.2124) radius 15 clockwise from (-48.5935, 209.2124) to (-33.5935, 224.2124)
  arc A2 centre (-9.0158, 20.6671) radius 82.5 clockwise from (30.5619, 93.054) to (-48.5935, 93.054)
  arc A3 centre (15.5619, 209.2124) radius 15 clockwise from (15.5619, 224.2124) to (30.5619, 209.2124)
  arc A4 centre (-19, 201.5) radius 1 clockwise from (-20, 201.5) to (-19, 202.5)
  arc A5 centre (-14.95, 200.2) radius 0.5 clockwise from (-15.45, 200.2) to (-14.95, 200.7)
  arc A6 centre (-14.95, 199.1071) radius 0.5 clockwise from (-15.3036, 198.7536) to (-15.45, 199.1071)
  arc A7 centre (-12.7429, 196.9) radius 0.5 clockwise from (-12.7429, 196.4) to (-13.0964, 196.5464)
  arc A8 centre (-7.2571, 196.9) radius 0.5 clockwise from (-6.9036, 196.5464) to (-7.2571, 196.4)
  arc A9 centre (-5.05, 199.1071) radius 0.5 clockwise from (-4.55, 199.1071) to (-4.6964, 198.7536)
  arc A10 centre (-5.05, 200.2) radius 0.5 clockwise from (-5.05, 200.7) to (-4.55, 200.2)
  arc A11 centre (-1, 201.5) radius 1 clockwise from (-1, 202.5) to (0, 201.5)
  arc A12 centre (-2.3, 197.45) radius 0.5 clockwise from (-2.3, 197.95) to (-1.8, 197.45)
  arc A13 centre (-3.3929, 197.45) radius 0.5 clockwise from (-3.7464, 197.8036) to (-3.3929, 197.95)
  arc A14 centre (-5.6, 195.2429) radius 0.5 clockwise from (-6.1, 195.2429) to (-5.9536, 195.5964)
  arc A15 centre (-5.6, 189.7571) radius 0.5 clockwise from (-5.9536, 189.4036) to (-6.1, 189.7571)
  arc A16 centre (-3.3929, 187.55) radius 0.5 clockwise from (-3.3929, 187.05) to (-3.7464, 187.1964)
  arc A17 centre (-2.3, 187.55) radius 0.5 clockwise from (-1.8, 187.55) to (-2.3, 187.05)
  arc A18 centre (-1, 183.5) radius 1 clockwise from (0, 183.5) to (-1, 182.5)
  arc A19 centre (-5.05, 184.8) radius 0.5 clockwise from (-4.55, 184.8) to (-5.05, 184.3)
  arc A20 centre (-5.05, 185.8929) radius 0.5 clockwise from (-4.6964, 186.2464) to (-4.55, 185.8929)
  arc A21 centre (-7.2571, 188.1) radius 0.5 clockwise from (-7.2571, 188.6) to (-6.9036, 188.4536)
  arc A22 centre (-12.7429, 188.1) radius 0.5 clockwise from (-13.0964, 188.4536) to (-12.7429, 188.6)
  arc A23 centre (-14.95, 185.8929) radius 0.5 clockwise from (-15.45, 185.8929) to (-15.3036, 186.2464)
  arc A24 centre (-14.95, 184.8) radius 0.5 clockwise from (-14.95, 184.3) to (-15.45, 184.8)
  arc A25 centre (-19, 183.5) radius 1 clockwise from (-19, 182.5) to (-20, 183.5)
  arc A26 centre (-17.7, 187.55) radius 0.5 clockwise from (-17.7, 187.05) to (-18.2, 187.55)
  arc A27 centre (-16.6071, 187.55) radius 0.5 clockwise from (-16.2536, 187.1964) to (-16.6071, 187.05)
  arc A28 centre (-14.4, 189.7571) radius 0.5 clockwise from (-13.9, 189.7571) to (-14.0464, 189.4036)
  arc A29 centre (-14.4, 195.2429) radius 0.5 clockwise from (-14.0464, 195.5964) to (-13.9, 195.2429)
  arc A30 centre (-16.6071, 197.45) radius 0.5 clockwise from (-16.6071, 197.95) to (-16.2536, 197.8036)
  arc A31 centre (-17.7, 197.45) radius 0.5 clockwise from (-18.2, 197.45) to (-17.7, 197.95)
  circle C1 centre (-9.0158, 20.6671) radius 78.8
  point P111 (30.5619, 135.0766)
  point P112 (-48.5935, 135.0766)
  coincident L2 P111
  coincident L1 P112
  perpendicular L1 L48
split "Split1"
sketch "Sketch9" plane through (0, 0, 107.9925) normal (0, 0, -1) x axis (-1, 0, 0)
sketch "Sketch10" plane through (0, 0, 107.9925) normal (0, 0, -1) x axis (-1, 0, 0)
  line L1 (-48.5935, -1.7411) -> (-48.5935, 32.5709)
  line L2 (30.5619, -1.7411) -> (-48.5935, -1.7411)
  line L3 (30.5619, 32.5709) -> (30.5619, -1.7411)
  line L4 (-48.5935, 32.5709) -> (30.5619, 32.5709)
  line L5 (-43.1719, 3.6805) -> (-43.1719, 27.1492)
  line L6 (25.1402, 3.6805) -> (-43.1719, 3.6805)
  line L7 (25.1402, 27.1492) -> (25.1402, 3.6805)
  line L8 (-43.1719, 27.1492) -> (25.1402, 27.1492)
  dimension "d154" = -5.4216
sketch "Sketch1" plane through (0, -1.7411, 0) normal (0, -1, 0) x axis (1, 0, 0)
  line L1 (20, 201.5) -> (20, 195.7)
  line L2 (13.2, 202.5) -> (19, 202.5)
  line L3 (13.2, 200.7) -> (13.2, 202.5)
  line L4 (14.95, 200.7) -> (13.2, 200.7)
  line L5 (15.45, 199.1071) -> (15.45, 200.2)
  line L6 (13.0964, 196.5464) -> (15.3036, 198.7536)
  line L7 (7.2571, 196.4) -> (12.7429, 196.4)
  line L8 (4.6964, 198.7536) -> (6.9036, 196.5464)
  line L9 (4.55, 200.2) -> (4.55, 199.1071)
  line L10 (6.8, 200.7) -> (5.05, 200.7)
  line L11 (6.8, 202.5) -> (6.8, 200.7)
  line L12 (1, 202.5) -> (6.8, 202.5)
  line L13 (0, 195.7) -> (0, 201.5)
  line L14 (1.8, 195.7) -> (0, 195.7)
  line L15 (1.8, 197.45) -> (1.8, 195.7)
  line L16 (3.3929, 197.95) -> (2.3, 197.95)
  line L17 (5.9536, 195.5964) -> (3.7464, 197.8036)
  line L18 (6.1, 189.7571) -> (6.1, 195.2429)
  line L19 (3.7464, 187.1964) -> (5.9536, 189.4036)
  line L20 (2.3, 187.05) -> (3.3929, 187.05)
  line L21 (1.8, 189.3) -> (1.8, 187.55)
  line L22 (0, 189.3) -> (1.8, 189.3)
  line L23 (0, 183.5) -> (0, 189.3)
  line L24 (6.8, 182.5) -> (1, 182.5)
  line L25 (6.8, 184.3) -> (6.8, 182.5)
  line L26 (5.05, 184.3) -> (6.8, 184.3)
  line L27 (4.55, 185.8929) -> (4.55, 184.8)
  line L28 (6.9036, 188.4536) -> (4.6964, 186.2464)
  line L29 (12.7429, 188.6) -> (7.2571, 188.6)
  line L30 (15.3036, 186.2464) -> (13.0964, 188.4536)
  line L31 (15.45, 184.8) -> (15.45, 185.8929)
  line L32 (13.2, 184.3) -> (14.95, 184.3)
  line L33 (13.2, 182.5) -> (13.2, 184.3)
  line L34 (19, 182.5) -> (13.2, 182.5)
  line L35 (20, 189.3) -> (20, 183.5)
  line L36 (18.2, 189.3) -> (20, 189.3)
  line L37 (18.2, 187.55) -> (18.2, 189.3)
  line L38 (16.6071, 187.05) -> (17.7, 187.05)
  line L39 (14.0464, 189.4036) -> (16.2536, 187.1964)
  line L40 (13.9, 195.2429) -> (13.9, 189.7571)
  line L41 (16.2536, 197.8036) -> (14.0464, 195.5964)
  line L42 (17.7, 197.95) -> (16.6071, 197.95)
  line L43 (18.2, 195.7) -> (18.2, 197.45)
  line L44 (20, 195.7) -> (18.2, 195.7)
  line L45 (13.05, 202.65) -> (19, 202.65)
  line L46 (13.05, 200.55) -> (13.05, 202.65)
  line L47 (14.95, 200.55) -> (13.05, 200.55)
  line L48 (15.3, 199.1071) -> (15.3, 200.2)
  line L49 (12.9904, 196.6525) -> (15.1975, 198.8596)
  line L50 (7.2571, 196.55) -> (12.7429, 196.55)
  line L51 (4.8025, 198.8596) -> (7.0096, 196.6525)
  line L52 (4.7, 200.2) -> (4.7, 199.1071)
  line L53 (6.95, 200.55) -> (5.05, 200.55)
  line L54 (6.95, 202.65) -> (6.95, 200.55)
  line L55 (1, 202.65) -> (6.95, 202.65)
  line L56 (-0.15, 195.55) -> (-0.15, 201.5)
  line L57 (1.95, 195.55) -> (-0.15, 195.55)
  line L58 (1.95, 197.45) -> (1.95, 195.55)
  line L59 (3.3929, 197.8) -> (2.3, 197.8)
  line L60 (5.8475, 195.4904) -> (3.6404, 197.6975)
  line L61 (5.95, 189.7571) -> (5.95, 195.2429)
  line L62 (3.6404, 187.3025) -> (5.8475, 189.5096)
  line L63 (2.3, 187.2) -> (3.3929, 187.2)
  line L64 (1.95, 189.45) -> (1.95, 187.55)
  line L65 (-0.15, 189.45) -> (1.95, 189.45)
  line L66 (-0.15, 183.5) -> (-0.15, 189.45)
  line L67 (6.95, 182.35) -> (1, 182.35)
  line L68 (6.95, 184.45) -> (6.95, 182.35)
  line L69 (5.05, 184.45) -> (6.95, 184.45)
  line L70 (4.7, 185.8929) -> (4.7, 184.8)
  line L71 (7.0096, 188.3475) -> (4.8025, 186.1404)
  line L72 (12.7429, 188.45) -> (7.2571, 188.45)
  line L73 (15.1975, 186.1404) -> (12.9904, 188.3475)
  line L74 (15.3, 184.8) -> (15.3, 185.8929)
  line L75 (13.05, 184.45) -> (14.95, 184.45)
  line L76 (13.05, 182.35) -> (13.05, 184.45)
  line L77 (19, 182.35) -> (13.05, 182.35)
  line L78 (20.15, 189.45) -> (20.15, 183.5)
  line L79 (18.05, 189.45) -> (20.15, 189.45)
  line L80 (18.05, 187.55) -> (18.05, 189.45)
  line L81 (16.6071, 187.2) -> (17.7, 187.2)
  line L82 (14.1525, 189.5096) -> (16.3596, 187.3025)
  line L83 (14.05, 195.2429) -> (14.05, 189.7571)
  line L84 (16.3596, 197.6975) -> (14.1525, 195.4904)
  line L85 (17.7, 197.8) -> (16.6071, 197.8)
  line L86 (18.05, 195.55) -> (18.05, 197.45)
  line L87 (20.15, 195.55) -> (18.05, 195.55)
  line L88 (20.15, 201.5) -> (20.15, 195.55)
  arc A1 centre (19, 201.5) radius 1 clockwise from (19, 202.5) to (20, 201.5)
  arc A2 centre (14.95, 200.2) radius 0.5 clockwise from (14.95, 200.7) to (15.45, 200.2)
  arc A3 centre (14.95, 199.1071) radius 0.5 clockwise from (15.45, 199.1071) to (15.3036, 198.7536)
  arc A4 centre (12.7429, 196.9) radius 0.5 clockwise from (13.0964, 196.5464) to (12.7429, 196.4)
  arc A5 centre (7.2571, 196.9) radius 0.5 clockwise from (7.2571, 196.4) to (6.9036, 196.5464)
  arc A6 centre (5.05, 199.1071) radius 0.5 clockwise from (4.6964, 198.7536) to (4.55, 199.1071)
  arc A7 centre (5.05, 200.2) radius 0.5 clockwise from (4.55, 200.2) to (5.05, 200.7)
  arc A8 centre (1, 201.5) radius 1 clockwise from (0, 201.5) to (1, 202.5)
  arc A9 centre (2.3, 197.45) radius 0.5 clockwise from (1.8, 197.45) to (2.3, 197.95)
  arc A10 centre (3.3929, 197.45) radius 0.5 clockwise from (3.3929, 197.95) to (3.7464, 197.8036)
  arc A11 centre (5.6, 195.2429) radius 0.5 clockwise from (5.9536, 195.5964) to (6.1, 195.2429)
  arc A12 centre (5.6, 189.7571) radius 0.5 clockwise from (6.1, 189.7571) to (5.9536, 189.4036)
  arc A13 centre (3.3929, 187.55) radius 0.5 clockwise from (3.7464, 187.1964) to (3.3929, 187.05)
  arc A14 centre (2.3, 187.55) radius 0.5 clockwise from (2.3, 187.05) to (1.8, 187.55)
  arc A15 centre (1, 183.5) radius 1 clockwise from (1, 182.5) to (0, 183.5)
  arc A16 centre (5.05, 184.8) radius 0.5 clockwise from (5.05, 184.3) to (4.55, 184.8)
  arc A17 centre (5.05, 185.8929) radius 0.5 clockwise from (4.55, 185.8929) to (4.6964, 186.2464)
  arc A18 centre (7.2571, 188.1) radius 0.5 clockwise from (6.9036, 188.4536) to (7.2571, 188.6)
  arc A19 centre (12.7429, 188.1) radius 0.5 clockwise from (12.7429, 188.6) to (13.0964, 188.4536)
  arc A20 centre (14.95, 185.8929) radius 0.5 clockwise from (15.3036, 186.2464) to (15.45, 185.8929)
  arc A21 centre (14.95, 184.8) radius 0.5 clockwise from (15.45, 184.8) to (14.95, 184.3)
  arc A22 centre (19, 183.5) radius 1 clockwise from (20, 183.5) to (19, 182.5)
  arc A23 centre (17.7, 187.55) radius 0.5 clockwise from (18.2, 187.55) to (17.7, 187.05)
  arc A24 centre (16.6071, 187.55) radius 0.5 clockwise from (16.6071, 187.05) to (16.2536, 187.1964)
  arc A25 centre (14.4, 189.7571) radius 0.5 clockwise from (14.0464, 189.4036) to (13.9, 189.7571)
  arc A26 centre (14.4, 195.2429) radius 0.5 clockwise from (13.9, 195.2429) to (14.0464, 195.5964)
  arc A27 centre (16.6071, 197.45) radius 0.5 clockwise from (16.2536, 197.8036) to (16.6071, 197.95)
  arc A28 centre (17.7, 197.45) radius 0.5 clockwise from (17.7, 197.95) to (18.2, 197.45)
  circle C1 centre (10, 192.5) radius 2.5
  arc A29 centre (14.95, 200.2) radius 0.35 clockwise from (14.95, 200.55) to (15.3, 200.2)
  arc A30 centre (14.95, 199.1071) radius 0.35 clockwise from (15.3, 199.1071) to (15.1975, 198.8596)
  arc A31 centre (12.7429, 196.9) radius 0.35 clockwise from (12.9904, 196.6525) to (12.7429, 196.55)
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  dimension "d155" = 0.15
extrude "Extrude8" cut sketch "Sketch1" against normal blind 34.312
extrude "Extrude9" add of existing geometry blind 6.934
extrude "Extrude10" add of existing geometry blind 6.934
fillet "Fillet4" radius 91.567
sketch "Sketch2" plane through (0, 39.5049, 0) normal (0, 1, 0) x axis (-1, 0, 0)
  line L1 (-20.15, 195.55) -> (-18.05, 195.55)
  line L2 (-20.15, 201.5) -> (-20.15, 195.55)
  line L3 (-13.05, 202.65) -> (-19, 202.65)
  line L4 (-13.05, 200.55) -> (-13.05, 202.65)
  line L5 (-14.95, 200.55) -> (-13.05, 200.55)
  line L6 (-15.3, 199.1071) -> (-15.3, 200.2)
  line L7 (-12.9904, 196.6525) -> (-15.1975, 198.8596)
  line L8 (-7.2571, 196.55) -> (-12.7429, 196.55)
  line L9 (-4.8025, 198.8596) -> (-7.0096, 196.6525)
  line L10 (-4.7, 200.2) -> (-4.7, 199.1071)
  line L11 (-6.95, 200.55) -> (-5.05, 200.55)
  line L12 (-6.95, 202.65) -> (-6.95, 200.55)
  line L13 (-1, 202.65) -> (-6.95, 202.65)
  line L14 (0.15, 195.55) -> (0.15, 201.5)
  line L15 (-1.95, 195.55) -> (0.15, 195.55)
  line L16 (-1.95, 197.45) -> (-1.95, 195.55)
  line L17 (-3.3929, 197.8) -> (-2.3, 197.8)
  line L18 (-5.8475, 195.4904) -> (-3.6404, 197.6975)
  line L19 (-5.95, 189.7571) -> (-5.95, 195.2429)
  line L20 (-3.6404, 187.3025) -> (-5.8475, 189.5096)
  line L21 (-2.3, 187.2) -> (-3.3929, 187.2)
  line L22 (-1.95, 189.45) -> (-1.95, 187.55)
  line L23 (0.15, 189.45) -> (-1.95, 189.45)
  line L24 (0.15, 183.5) -> (0.15, 189.45)
  line L25 (-6.95, 182.35) -> (-1, 182.35)
  line L26 (-6.95, 184.45) -> (-6.95, 182.35)
  line L27 (-5.05, 184.45) -> (-6.95, 184.45)
  line L28 (-4.7, 185.8929) -> (-4.7, 184.8)
  line L29 (-7.0096, 188.3475) -> (-4.8025, 186.1404)
  line L30 (-12.7429, 188.45) -> (-7.2571, 188.45)
  line L31 (-15.1975, 186.1404) -> (-12.9904, 188.3475)
  line L32 (-15.3, 184.8) -> (-15.3, 185.8929)
  line L33 (-13.05, 184.45) -> (-14.95, 184.45)
  line L34 (-13.05, 182.35) -> (-13.05, 184.45)
  line L35 (-19, 182.35) -> (-13.05, 182.35)
  line L36 (-20.15, 189.45) -> (-20.15, 183.5)
  line L37 (-18.05, 189.45) -> (-20.15, 189.45)
  line L38 (-18.05, 187.55) -> (-18.05, 189.45)
  line L39 (-16.6071, 187.2) -> (-17.7, 187.2)
  line L40 (-14.1525, 189.5096) -> (-16.3596, 187.3025)
  line L41 (-14.05, 195.2429) -> (-14.05, 189.7571)
  line L42 (-16.3596, 197.6975) -> (-14.1525, 195.4904)
  line L43 (-17.7, 197.8) -> (-16.6071, 197.8)
  line L44 (-18.05, 195.55) -> (-18.05, 197.45)
  line L45 (30.5619, 209.2124) -> (30.5619, 135.124)
  line L46 (-33.5935, 224.2124) -> (15.5619, 224.2124)
  line L47 (-48.5935, 135.124) -> (-48.5935, 209.2124)
  circle C1 centre (-9.0158, 20.6671) radius 78.8
  arc A1 centre (-19, 201.5) radius 1.15 clockwise from (-20.15, 201.5) to (-19, 202.65)
  arc A2 centre (-14.95, 200.2) radius 0.35 clockwise from (-15.3, 200.2) to (-14.95, 200.55)
  arc A3 centre (-14.95, 199.1071) radius 0.35 clockwise from (-15.1975, 198.8596) to (-15.3, 199.1071)
  arc A4 centre (-12.7429, 196.9) radius 0.35 clockwise from (-12.7429, 196.55) to (-12.9904, 196.6525)
  arc A5 centre (-7.2571, 196.9) radius 0.35 clockwise from (-7.0096, 196.6525) to (-7.2571, 196.55)
  arc A6 centre (-5.05, 199.1071) radius 0.35 clockwise from (-4.7, 199.1071) to (-4.8025, 198.8596)
  arc A7 centre (-5.05, 200.2) radius 0.35 clockwise from (-5.05, 200.55) to (-4.7, 200.2)
  arc A8 centre (-1, 201.5) radius 1.15 clockwise from (-1, 202.65) to (0.15, 201.5)
  arc A9 centre (-2.3, 197.45) radius 0.35 clockwise from (-2.3, 197.8) to (-1.95, 197.45)
  arc A10 centre (-3.3929, 197.45) radius 0.35 clockwise from (-3.6404, 197.6975) to (-3.3929, 197.8)
  arc A11 centre (-5.6, 195.2429) radius 0.35 clockwise from (-5.95, 195.2429) to (-5.8475, 195.4904)
  arc A12 centre (-5.6, 189.7571) radius 0.35 clockwise from (-5.8475, 189.5096) to (-5.95, 189.7571)
  arc A13 centre (-3.3929, 187.55) radius 0.35 clockwise from (-3.3929, 187.2) to (-3.6404, 187.3025)
  arc A14 centre (-2.3, 187.55) radius 0.35 clockwise from (-1.95, 187.55) to (-2.3, 187.2)
  arc A15 centre (-1, 183.5) radius 1.15 clockwise from (0.15, 183.5) to (-1, 182.35)
  arc A16 centre (-5.05, 184.8) radius 0.35 clockwise from (-4.7, 184.8) to (-5.05, 184.45)
  arc A17 centre (-5.05, 185.8929) radius 0.35 clockwise from (-4.8025, 186.1404) to (-4.7, 185.8929)
  arc A18 centre (-7.2571, 188.1) radius 0.35 clockwise from (-7.2571, 188.45) to (-7.0096, 188.3475)
  arc A19 centre (-12.7429, 188.1) radius 0.35 clockwise from (-12.9904, 188.3475) to (-12.7429, 188.45)
  arc A20 centre (-14.95, 185.8929) radius 0.35 clockwise from (-15.3, 185.8929) to (-15.1975, 186.1404)
  arc A21 centre (-14.95, 184.8) radius 0.35 clockwise from (-14.95, 184.45) to (-15.3, 184.8)
  arc A22 centre (-19, 183.5) radius 1.15 clockwise from (-19, 182.35) to (-20.15, 183.5)
  arc A23 centre (-17.7, 187.55) radius 0.35 clockwise from (-17.7, 187.2) to (-18.05, 187.55)
  arc A24 centre (-16.6071, 187.55) radius 0.35 clockwise from (-16.3596, 187.3025) to (-16.6071, 187.2)
  arc A25 centre (-14.4, 189.7571) radius 0.35 clockwise from (-14.05, 189.7571) to (-14.1525, 189.5096)
  arc A26 centre (-14.4, 195.2429) radius 0.35 clockwise from (-14.1525, 195.4904) to (-14.05, 195.2429)
  arc A27 centre (-16.6071, 197.45) radius 0.35 clockwise from (-16.6071, 197.8) to (-16.3596, 197.6975)
  arc A28 centre (-17.7, 197.45) radius 0.35 clockwise from (-18.05, 197.45) to (-17.7, 197.8)
  arc A29 centre (15.5619, 209.2124) radius 15 clockwise from (15.5619, 224.2124) to (30.5619, 209.2124)
  arc A30 centre (-33.5935, 209.2124) radius 15 clockwise from (-48.5935, 209.2124) to (-33.5935, 224.2124)
  arc A31 centre (-140.1605, 135.124) radius 91.567 clockwise from (-48.5935, 135.124) to (-71.1726, 74.9146)
  arc A32 centre (-9.0158, 20.6671) radius 82.5 clockwise from (53.1409, 74.9146) to (-71.1726, 74.9146)
  arc A33 centre (122.1289, 135.124) radius 91.567 clockwise from (53.1409, 74.9146) to (30.5619, 135.124)
  circle C2 centre (-9.0158, 20.6671) radius 87.2896
  dimension "d164" = 8.4896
